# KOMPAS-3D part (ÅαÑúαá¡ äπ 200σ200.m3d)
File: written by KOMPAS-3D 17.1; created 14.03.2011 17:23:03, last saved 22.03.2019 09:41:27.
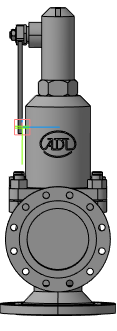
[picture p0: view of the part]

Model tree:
1. Плоскость XY
2. Плоскость ZX
3. Плоскость ZY
4. Ось X
5. Ось Y
6. Ось Z
7. Начало координат
8. Операция без истории:2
